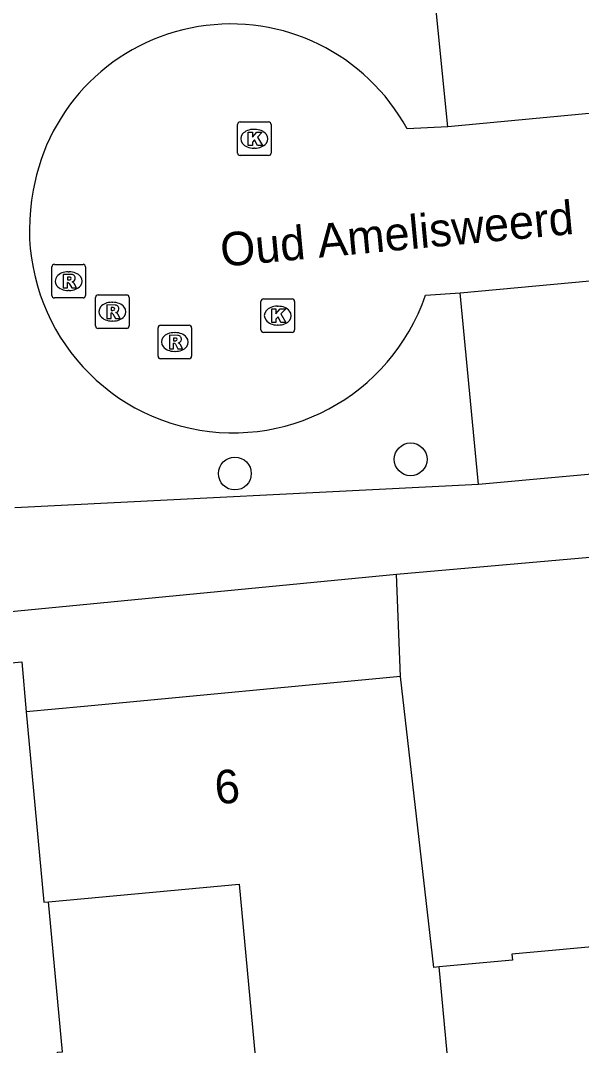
# Model space of a CAD drawing. Extents: x 157793 to 159380, y 380882 to 382313.
# Drawn here: x 158403.74 to 158420.44, y 381200.87 to 381231.4 of the extents above; entities that cross this region are included whole.
import ezdxf

# ---------------------------------------------------------------- set-up
doc = ezdxf.new("R2010")
doc.units = 0
for name, color, linetype in [('IMGEO_Boom', 7, 'Continuous'), ('IMGEO_Kolk', 7, 'Continuous'), ('IMGEO_Openbare_ruimte_label', 7, 'Continuous'), ('IMGEO_Pand', 7, 'Continuous'), ('IMGEO_Pand_nummerreeks', 7, 'Continuous'), ('IMGEO_Rijbaan_lokaal_open', 7, 'Continuous'), ('IMGEO_Rioolput', 7, 'Continuous'), ('IMGEO_Voetpad_open', 7, 'Continuous')]:
    doc.layers.add(name, color=color, linetype=linetype)

msp = doc.modelspace()

# ---------------------------------------------------------------- linework, layer by layer
at = {"layer": 'IMGEO_Boom'}
for centre in [(158415.353, 381218.326), (158410.121, 381217.902)]:
    msp.add_circle(centre, 0.489, dxfattribs=at)
at = {"layer": 'IMGEO_Kolk'}
for p, q in [((158410.199, 381227.448), (158410.199, 381228.3)), ((158410.274, 381228.374), (158411.126, 381228.374)), ((158411.2, 381228.3), (158411.2, 381227.448)), ((158410.687, 381228.154), (158410.712, 381228.154)), ((158410.71, 381227.594), (158410.685, 381227.594)), ((158411.126, 381227.374), (158410.274, 381227.374)), ((158410.897, 381222.179), (158410.897, 381223.031)), ((158410.972, 381223.105), (158411.824, 381223.105)), ((158411.898, 381223.031), (158411.898, 381222.179)), ((158411.385, 381222.885), (158411.41, 381222.885)), ((158411.824, 381222.105), (158410.972, 381222.105)), ((158411.408, 381222.325), (158411.383, 381222.325))]:
    msp.add_line(p, q, dxfattribs=at)
for points in [[(158410.199, 381227.448), (158410.199, 381228.3)], [(158410.274, 381228.374), (158411.126, 381228.374)], [(158411.2, 381228.3), (158411.2, 381227.448)], [(158410.52, 381228.074), (158410.643, 381228.074), (158410.643, 381227.923), (158410.773, 381228.074), (158410.937, 381228.074), (158410.791, 381227.923), (158410.944, 381227.674), (158410.792, 381227.674), (158410.707, 381227.838), (158410.643, 381227.771), (158410.643, 381227.674), (158410.52, 381227.674), (158410.52, 381228.074)], [(158411.126, 381227.374), (158410.274, 381227.374)], [(158410.897, 381222.179), (158410.897, 381223.031)], [(158410.972, 381223.105), (158411.824, 381223.105)], [(158411.898, 381223.031), (158411.898, 381222.179)], [(158411.218, 381222.805), (158411.341, 381222.805), (158411.341, 381222.654), (158411.471, 381222.805), (158411.635, 381222.805), (158411.489, 381222.654), (158411.642, 381222.405), (158411.49, 381222.405), (158411.405, 381222.569), (158411.341, 381222.502), (158411.341, 381222.405), (158411.218, 381222.405), (158411.218, 381222.805)], [(158411.824, 381222.105), (158410.972, 381222.105)]]:
    msp.add_lwpolyline(points, dxfattribs=at)
for centre, start, end in [((158410.276, 381228.298), 91.552, 178.448), ((158410.276, 381228.298), 91.552, 178.448), ((158411.124, 381228.298), 1.552, 88.448), ((158411.124, 381228.298), 1.552, 88.448), ((158410.276, 381227.45), 181.552, 268.448), ((158410.276, 381227.45), 181.552, 268.448), ((158411.124, 381227.45), 271.552, 358.448), ((158411.124, 381227.45), 271.552, 358.448), ((158410.974, 381223.029), 91.552, 178.448), ((158410.974, 381223.029), 91.552, 178.448), ((158411.822, 381223.029), 1.552, 88.448), ((158411.822, 381223.029), 1.552, 88.448), ((158410.974, 381222.181), 181.552, 268.448), ((158410.974, 381222.181), 181.552, 268.448), ((158411.822, 381222.181), 271.552, 358.448), ((158411.822, 381222.181), 271.552, 358.448)]:
    msp.add_arc(centre, 0.0765, start, end, dxfattribs=at)
for centre, major_axis, ratio, start_param, end_param in [((158410.686, 381227.874), (-0.387, 0.002), 0.722429, 4.712389, 7.853982), ((158410.711, 381227.874), (-0.39, 0.002), 0.717154, 1.570796, 4.712389), ((158411.384, 381222.605), (-0.387, 0.002), 0.722429, 4.712389, 7.853982), ((158411.409, 381222.605), (-0.39, 0.002), 0.717154, 1.570796, 4.712389)]:
    msp.add_ellipse(centre, major_axis=major_axis, ratio=ratio, start_param=start_param, end_param=end_param, dxfattribs=at)
at = {"layer": 'IMGEO_Pand'}
for points in [[(158414.936, 381214.906), (158426.439, 381215.918)], [(158415.056, 381211.859), (158414.936, 381214.906)], [(158392.373, 381211.219), (158392.521, 381211.233), (158394.742, 381211.443), (158403.775, 381212.297), (158403.911, 381210.806)], [(158415.056, 381211.859), (158405.635, 381210.969), (158403.911, 381210.806)], [(158416.207, 381203.208), (158416.047, 381203.193), (158415.056, 381211.859)], [(158403.911, 381210.806), (158404.429, 381205.133), (158404.572, 381205.146)], [(158404.572, 381205.146), (158410.252, 381205.67), (158410.802, 381199.701), (158411.019, 381197.349)], [(158405.19, 381196.824), (158404.836, 381200.668), (158404.985, 381200.68), (158404.572, 381205.146)], [(158421.515, 381203.992), (158421.525, 381203.881), (158418.369, 381203.587), (158418.385, 381203.408), (158416.207, 381203.208)], [(158416.539, 381197.859), (158416.321, 381200.21), (158416.482, 381200.225), (158416.207, 381203.208)]]:
    msp.add_lwpolyline(points, dxfattribs=at)
at = {"layer": 'IMGEO_Rijbaan_lokaal_open'}
for points in [[(158434.025, 381229.887), (158416.46, 381228.231)], [(158416.46, 381228.231), (158415.248, 381228.166)], [(158416.824, 381223.289), (158426.913, 381224.222)], [(158415.796, 381223.213), (158416.824, 381223.289)]]:
    msp.add_lwpolyline(points, dxfattribs=at)
for centre, radius, start, end in [((158410, 381225.322), 5.969, 28.4562, 170.1794), ((158410.064, 381225.173), 6.058, 168.8941, 341.1228)]:
    msp.add_arc(centre, radius, start, end, dxfattribs=at)
at = {"layer": 'IMGEO_Rioolput'}
for p, q in [((158404.673, 381223.207), (158404.673, 381224.059)), ((158404.748, 381224.133), (158405.6, 381224.133)), ((158405.161, 381223.913), (158405.186, 381223.913)), ((158405.674, 381224.059), (158405.674, 381223.207)), ((158405.184, 381223.353), (158405.159, 381223.353)), ((158405.6, 381223.133), (158404.748, 381223.133)), ((158405.973, 381222.298), (158405.973, 381223.15)), ((158406.048, 381223.224), (158406.9, 381223.224)), ((158406.461, 381223.004), (158406.486, 381223.004)), ((158406.974, 381223.15), (158406.974, 381222.298)), ((158406.484, 381222.444), (158406.459, 381222.444)), ((158406.9, 381222.224), (158406.048, 381222.224)), ((158407.833, 381221.394), (158407.833, 381222.246)), ((158407.908, 381222.32), (158408.76, 381222.32)), ((158408.321, 381222.1), (158408.346, 381222.1)), ((158408.834, 381222.246), (158408.834, 381221.394)), ((158408.344, 381221.54), (158408.319, 381221.54)), ((158408.76, 381221.32), (158407.908, 381221.32))]:
    msp.add_line(p, q, dxfattribs=at)
for points in [[(158404.673, 381223.207), (158404.673, 381224.059)], [(158404.748, 381224.133), (158405.6, 381224.133)], [(158405.674, 381224.059), (158405.674, 381223.207)], [(158405.262, 381223.831), (158405.01, 381223.833), (158405.01, 381223.433)], [(158405.188, 381223.752), (158405.134, 381223.752), (158405.134, 381223.671)], [(158405.134, 381223.671), (158405.186, 381223.671)], [(158405.01, 381223.433), (158405.134, 381223.433), (158405.134, 381223.595), (158405.145, 381223.595)], [(158405.192, 381223.566), (158405.263, 381223.433), (158405.403, 381223.433), (158405.338, 381223.559)], [(158405.6, 381223.133), (158404.748, 381223.133)], [(158405.973, 381222.298), (158405.973, 381223.15)], [(158406.048, 381223.224), (158406.9, 381223.224)], [(158406.974, 381223.15), (158406.974, 381222.298)], [(158406.562, 381222.922), (158406.31, 381222.924), (158406.31, 381222.524)], [(158406.31, 381222.524), (158406.434, 381222.524), (158406.434, 381222.686), (158406.445, 381222.686)], [(158406.488, 381222.843), (158406.434, 381222.843), (158406.434, 381222.762)], [(158406.434, 381222.762), (158406.486, 381222.762)], [(158406.492, 381222.657), (158406.563, 381222.524), (158406.703, 381222.524), (158406.638, 381222.65)], [(158406.9, 381222.224), (158406.048, 381222.224)], [(158407.833, 381221.394), (158407.833, 381222.246)], [(158407.908, 381222.32), (158408.76, 381222.32)], [(158408.834, 381222.246), (158408.834, 381221.394)], [(158408.422, 381222.018), (158408.17, 381222.02), (158408.17, 381221.62)], [(158408.17, 381221.62), (158408.294, 381221.62), (158408.294, 381221.782), (158408.305, 381221.782)], [(158408.348, 381221.939), (158408.294, 381221.939), (158408.294, 381221.858)], [(158408.294, 381221.858), (158408.346, 381221.858)], [(158408.352, 381221.753), (158408.423, 381221.62), (158408.563, 381221.62), (158408.498, 381221.746)], [(158408.76, 381221.32), (158407.908, 381221.32)]]:
    msp.add_lwpolyline(points, dxfattribs=at)
for centre, radius, start, end in [((158404.75, 381224.057), 0.0765, 91.552, 178.448), ((158404.75, 381224.057), 0.0765, 91.552, 178.448), ((158405.598, 381224.057), 0.0765, 1.552, 88.448), ((158405.598, 381224.057), 0.0765, 1.552, 88.448), ((158405.17, 381223.86), 0.19, 274.7715, 282.9687), ((158405.194, 381223.656), 0.0964, 77.0061, 93.1865), ((158405.208, 381223.713), 0.0378, 276.6634, 79.6772), ((158405.261, 381223.721), 0.109, 350.3612, 89.416), ((158405.259, 381223.721), 0.112, 277.5842, 350.9817), ((158405.243, 381223.506), 0.108, 29.5134, 73.7905), ((158405.144, 381223.542), 0.0533, 26.0293, 88.6989), ((158404.75, 381223.209), 0.0765, 181.552, 268.448), ((158404.75, 381223.209), 0.0765, 181.552, 268.448), ((158405.598, 381223.209), 0.0765, 271.552, 358.448), ((158405.598, 381223.209), 0.0765, 271.552, 358.448), ((158406.05, 381223.148), 0.0765, 91.552, 178.448), ((158406.05, 381223.148), 0.0765, 91.552, 178.448), ((158406.898, 381223.148), 0.0765, 1.552, 88.448), ((158406.898, 381223.148), 0.0765, 1.552, 88.448), ((158406.444, 381222.633), 0.0533, 26.0293, 88.6989), ((158406.47, 381222.951), 0.19, 274.7715, 282.9687), ((158406.494, 381222.747), 0.0964, 77.0061, 93.1865), ((158406.508, 381222.804), 0.0378, 276.6634, 79.6772), ((158406.561, 381222.812), 0.109, 350.3612, 89.416), ((158406.559, 381222.812), 0.112, 277.5842, 350.9817), ((158406.543, 381222.597), 0.108, 29.5134, 73.7905), ((158406.05, 381222.3), 0.0765, 181.552, 268.448), ((158406.05, 381222.3), 0.0765, 181.552, 268.448), ((158406.898, 381222.3), 0.0765, 271.552, 358.448), ((158406.898, 381222.3), 0.0765, 271.552, 358.448), ((158407.91, 381222.244), 0.0765, 91.552, 178.448), ((158407.91, 381222.244), 0.0765, 91.552, 178.448), ((158408.758, 381222.244), 0.0765, 1.552, 88.448), ((158408.758, 381222.244), 0.0765, 1.552, 88.448), ((158408.304, 381221.729), 0.0533, 26.0293, 88.6989), ((158408.33, 381222.047), 0.19, 274.7715, 282.9687), ((158408.354, 381221.843), 0.0964, 77.0061, 93.1865), ((158408.368, 381221.9), 0.0378, 276.6634, 79.6772), ((158408.421, 381221.908), 0.109, 350.3612, 89.416), ((158408.419, 381221.908), 0.112, 277.5842, 350.9817), ((158408.403, 381221.693), 0.108, 29.5134, 73.7905), ((158407.91, 381221.396), 0.0765, 181.552, 268.448), ((158407.91, 381221.396), 0.0765, 181.552, 268.448), ((158408.758, 381221.396), 0.0765, 271.552, 358.448), ((158408.758, 381221.396), 0.0765, 271.552, 358.448)]:
    msp.add_arc(centre, radius, start, end, dxfattribs=at)
for centre, major_axis, ratio, start_param, end_param in [((158405.16, 381223.633), (-0.387, 0.002), 0.722429, 4.712389, 7.853982), ((158405.185, 381223.633), (-0.39, 0.002), 0.717154, 1.570796, 4.712389), ((158406.46, 381222.724), (-0.387, 0.002), 0.722429, 4.712389, 7.853982), ((158406.485, 381222.724), (-0.39, 0.002), 0.717154, 1.570796, 4.712389), ((158408.32, 381221.82), (-0.387, 0.002), 0.722429, 4.712389, 7.853982), ((158408.345, 381221.82), (-0.39, 0.002), 0.717154, 1.570796, 4.712389)]:
    msp.add_ellipse(centre, major_axis=major_axis, ratio=ratio, start_param=start_param, end_param=end_param, dxfattribs=at)
at = {"layer": 'IMGEO_Voetpad_open'}
for points in [[(158416.46, 381228.231), (158415.915, 381233.688), (158433.421, 381235.303), (158433.857, 381230.192), (158433.976, 381230.217)], [(158417.373, 381217.577), (158416.824, 381223.289)], [(158427.485, 381218.497), (158417.373, 381217.577)], [(158417.373, 381217.577), (158403.568, 381216.879)], [(158392.251, 381212.713), (158392.379, 381212.725), (158414.936, 381214.906)]]:
    msp.add_lwpolyline(points, dxfattribs=at)

# ---------------------------------------------------------------- texts
at = {"layer": 'IMGEO_Openbare_ruimte_label'}
msp.add_text('Oud Amelisweerd', height=1, rotation=5.3344, dxfattribs=at).set_placement((158409.735, 381224.06))
at = {"layer": 'IMGEO_Pand_nummerreeks'}
msp.add_text('6', height=1, rotation=5.3973, dxfattribs=at).set_placement((158409.567, 381208.046))

doc.saveas('drawing.dxf')
